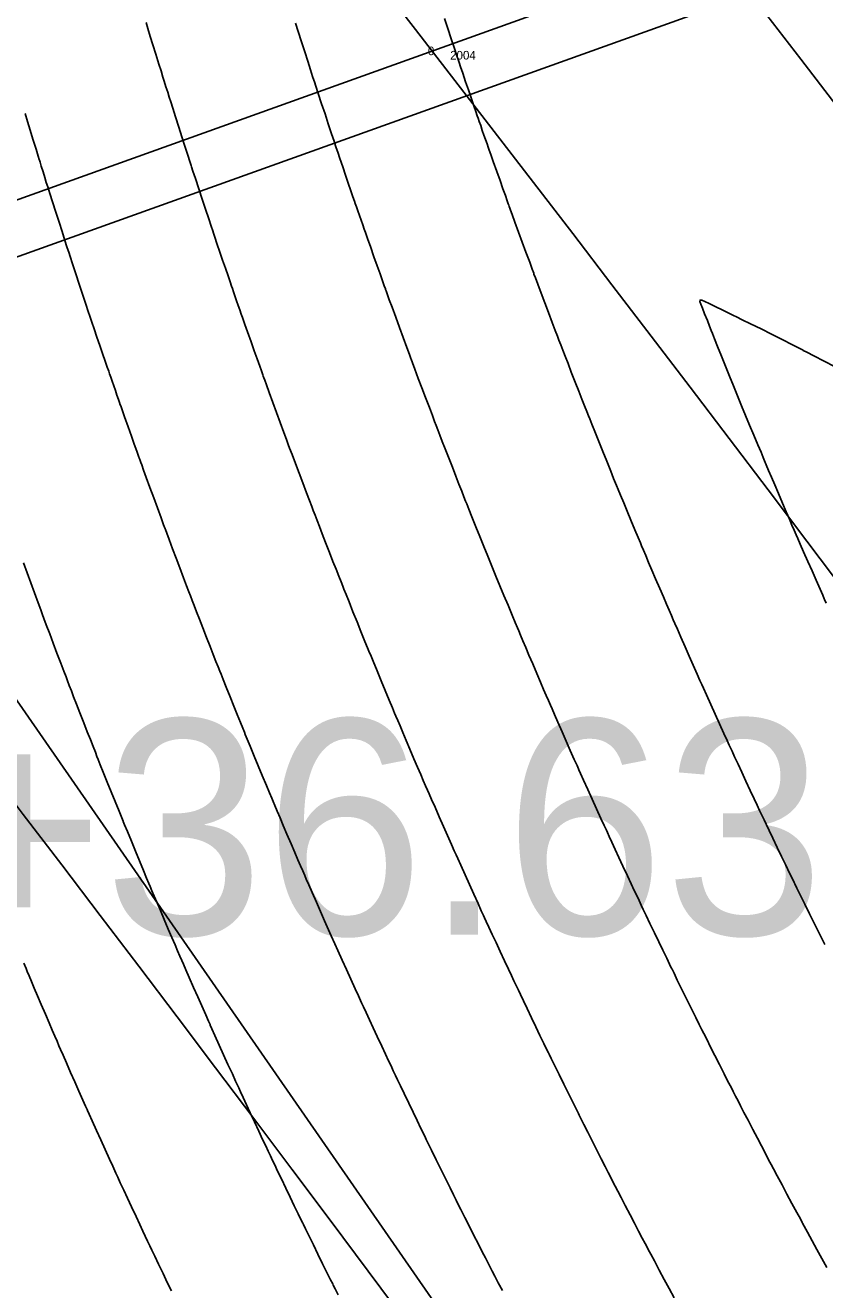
# Model space of a CAD drawing. Extents: x 74655 to 77873, y 48844 to 50507.
# Drawn here: x 75144.92 to 75156.06, y 49763.79 to 49781.42 of the extents above; entities that cross this region are included whole.
import ezdxf

# ---------------------------------------------------------------- set-up
doc = ezdxf.new("R2010")
doc.units = 0
for name, color, linetype in [('2', 7, 'Continuous'), ('24', 7, 'Continuous'), ('5', 7, 'Continuous'), ('50', 7, 'Continuous'), ('62', 7, 'Continuous'), ('7', 7, 'Continuous')]:
    doc.layers.add(name, color=color, linetype=linetype)

msp = doc.modelspace()

# ---------------------------------------------------------------- linework, layer by layer
at = {"layer": '2'}
for radius in [833.511, 829.511, 818.511, 807.511, 803.511]:
    msp.add_arc((74494.001, 49274.129), radius, 30.805045, 46.697858, dxfattribs=at)
at = {"layer": '5'}
msp.add_line((75052.613, 49904.932), (75166.591, 49740.588), dxfattribs=at)
at = {"layer": '50'}
for points in [[(75146.602, 49781.459), (75146.628, 49781.374), (75146.661, 49781.265), (75146.698, 49781.146), (75146.738, 49781.017), (75146.781, 49780.878), (75146.81, 49780.783), (75146.825, 49780.733), (75146.827, 49780.728), (75146.837, 49780.697), (75146.854, 49780.642), (75146.879, 49780.561), (75146.903, 49780.486), (75146.924, 49780.417), (75146.945, 49780.353), (75146.973, 49780.262), (75147.011, 49780.144), (75147.057, 49780), (75147.101, 49779.863), (75147.143, 49779.732), (75147.183, 49779.608), (75147.211, 49779.519), (75147.229, 49779.465), (75147.235, 49779.445), (75147.255, 49779.384), (75147.289, 49779.282), (75147.336, 49779.139), (75147.383, 49778.997), (75147.429, 49778.857), (75147.475, 49778.719), (75147.509, 49778.617), (75147.531, 49778.552), (75147.541, 49778.523), (75147.56, 49778.465), (75147.59, 49778.376), (75147.63, 49778.258), (75147.669, 49778.143), (75147.707, 49778.032), (75147.744, 49777.924), (75147.773, 49777.841), (75147.793, 49777.782), (75147.805, 49777.748), (75147.821, 49777.702), (75147.84, 49777.646), (75147.864, 49777.579), (75147.886, 49777.514), (75147.908, 49777.451), (75147.929, 49777.39), (75147.945, 49777.345), (75147.955, 49777.316), (75147.96, 49777.302), (75147.98, 49777.246), (75148.015, 49777.147), (75148.065, 49777.006), (75148.11, 49776.879), (75148.15, 49776.767), (75148.185, 49776.669), (75148.209, 49776.6), (75148.224, 49776.559), (75148.228, 49776.547), (75148.235, 49776.528), (75148.244, 49776.504), (75148.255, 49776.473), (75148.279, 49776.405), (75148.317, 49776.302), (75148.368, 49776.161), (75148.42, 49776.021), (75148.471, 49775.881), (75148.523, 49775.74), (75148.559, 49775.643), (75148.579, 49775.588), (75148.583, 49775.576), (75148.602, 49775.525), (75148.636, 49775.436), (75148.683, 49775.309), (75148.733, 49775.177), (75148.784, 49775.042), (75148.837, 49774.903), (75148.879, 49774.792), (75148.91, 49774.709), (75148.931, 49774.654), (75148.956, 49774.59), (75148.985, 49774.515), (75149.017, 49774.431), (75149.057, 49774.329), (75149.104, 49774.209), (75149.158, 49774.07), (75149.206, 49773.945), (75149.25, 49773.835), (75149.288, 49773.738), (75149.319, 49773.66), (75149.342, 49773.6), (75149.359, 49773.559), (75149.388, 49773.485), (75149.43, 49773.38), (75149.485, 49773.242), (75149.541, 49773.104), (75149.596, 49772.967), (75149.652, 49772.83), (75149.689, 49772.738), (75149.708, 49772.692), (75149.708, 49772.691), (75149.727, 49772.645), (75149.765, 49772.554), (75149.82, 49772.418), (75149.877, 49772.282), (75149.933, 49772.145), (75149.99, 49772.009), (75150.034, 49771.904), (75150.065, 49771.83), (75150.083, 49771.787), (75150.108, 49771.728), (75150.14, 49771.651), (75150.18, 49771.558), (75150.225, 49771.45), (75150.277, 49771.329), (75150.335, 49771.193), (75150.386, 49771.075), (75150.429, 49770.974), (75150.465, 49770.89), (75150.497, 49770.817), (75150.524, 49770.755), (75150.546, 49770.703), (75150.581, 49770.624), (75150.628, 49770.517), (75150.687, 49770.382), (75150.745, 49770.25), (75150.801, 49770.122), (75150.857, 49769.998), (75150.895, 49769.912), (75150.916, 49769.864), (75150.921, 49769.853), (75150.944, 49769.802), (75150.986, 49769.709), (75151.046, 49769.575), (75151.107, 49769.441), (75151.167, 49769.308), (75151.228, 49769.174), (75151.273, 49769.074), (75151.303, 49769.009), (75151.317, 49768.978), (75151.342, 49768.924), (75151.379, 49768.845), (75151.426, 49768.743), (75151.478, 49768.63), (75151.535, 49768.507), (75151.597, 49768.375), (75151.65, 49768.262), (75151.693, 49768.17), (75151.727, 49768.099), (75151.759, 49768.031), (75151.789, 49767.967), (75151.818, 49767.906), (75151.859, 49767.821), (75151.91, 49767.712), (75151.974, 49767.58), (75152.034, 49767.455), (75152.09, 49767.337), (75152.144, 49767.226), (75152.183, 49767.145), (75152.208, 49767.094), (75152.218, 49767.074), (75152.246, 49767.016), (75152.292, 49766.922), (75152.357, 49766.79), (75152.421, 49766.659), (75152.486, 49766.528), (75152.551, 49766.397), (75152.597, 49766.304), (75152.625, 49766.247), (75152.635, 49766.227), (75152.66, 49766.177), (75152.701, 49766.097), (75152.756, 49765.986), (75152.816, 49765.869), (75152.878, 49765.745), (75152.944, 49765.615), (75152.998, 49765.509), (75153.041, 49765.426), (75153.071, 49765.366), (75153.103, 49765.304), (75153.138, 49765.237), (75153.174, 49765.166), (75153.221, 49765.076), (75153.277, 49764.967), (75153.345, 49764.837), (75153.407, 49764.718), (75153.463, 49764.61), (75153.515, 49764.511), (75153.555, 49764.436), (75153.583, 49764.383), (75153.599, 49764.352), (75153.633, 49764.289), (75153.684, 49764.193), (75153.752, 49764.064), (75153.82, 49763.936), (75153.889, 49763.808), (75153.958, 49763.68)], [(75156.088, 49764.101), (75156.018, 49764.229), (75155.949, 49764.353), (75155.883, 49764.475), (75155.818, 49764.594), (75155.773, 49764.676), (75155.749, 49764.721), (75155.744, 49764.73), (75155.718, 49764.779), (75155.67, 49764.867), (75155.601, 49764.995), (75155.532, 49765.123), (75155.464, 49765.252), (75155.395, 49765.38), (75155.345, 49765.476), (75155.311, 49765.539), (75155.295, 49765.57), (75155.267, 49765.623), (75155.227, 49765.699), (75155.175, 49765.797), (75155.119, 49765.906), (75155.057, 49766.025), (75154.989, 49766.154), (75154.932, 49766.264), (75154.886, 49766.354), (75154.85, 49766.424), (75154.815, 49766.491), (75154.783, 49766.554), (75154.753, 49766.613), (75154.71, 49766.696), (75154.656, 49766.802), (75154.59, 49766.932), (75154.528, 49767.056), (75154.468, 49767.173), (75154.413, 49767.284), (75154.372, 49767.365), (75154.347, 49767.415), (75154.337, 49767.434), (75154.309, 49767.491), (75154.263, 49767.585), (75154.198, 49767.716), (75154.133, 49767.847), (75154.069, 49767.978), (75154.004, 49768.109), (75153.958, 49768.203), (75153.93, 49768.261), (75153.92, 49768.281), (75153.895, 49768.332), (75153.856, 49768.413), (75153.802, 49768.524), (75153.745, 49768.642), (75153.685, 49768.767), (75153.622, 49768.899), (75153.57, 49769.008), (75153.53, 49769.093), (75153.501, 49769.154), (75153.471, 49769.219), (75153.438, 49769.286), (75153.405, 49769.358), (75153.362, 49769.45), (75153.309, 49769.562), (75153.247, 49769.695), (75153.19, 49769.817), (75153.138, 49769.93), (75153.091, 49770.032), (75153.054, 49770.111), (75153.029, 49770.166), (75153.015, 49770.197), (75152.985, 49770.262), (75152.94, 49770.361), (75152.879, 49770.495), (75152.818, 49770.629), (75152.758, 49770.763), (75152.698, 49770.897), (75152.656, 49770.989), (75152.633, 49771.041), (75152.628, 49771.051), (75152.607, 49771.099), (75152.569, 49771.185), (75152.513, 49771.31), (75152.457, 49771.438), (75152.399, 49771.569), (75152.34, 49771.704), (75152.293, 49771.811), (75152.258, 49771.89), (75152.236, 49771.942), (75152.209, 49772.004), (75152.177, 49772.077), (75152.141, 49772.161), (75152.098, 49772.262), (75152.047, 49772.38), (75151.989, 49772.516), (75151.937, 49772.638), (75151.892, 49772.745), (75151.852, 49772.839), (75151.82, 49772.915), (75151.795, 49772.975), (75151.777, 49773.017), (75151.746, 49773.091), (75151.702, 49773.196), (75151.645, 49773.333), (75151.589, 49773.469), (75151.532, 49773.605), (75151.476, 49773.741), (75151.439, 49773.832), (75151.42, 49773.878), (75151.42, 49773.879), (75151.401, 49773.925), (75151.364, 49774.017), (75151.308, 49774.154), (75151.253, 49774.292), (75151.197, 49774.429), (75151.142, 49774.567), (75151.1, 49774.673), (75151.071, 49774.746), (75151.054, 49774.787), (75151.031, 49774.847), (75151, 49774.925), (75150.962, 49775.022), (75150.918, 49775.133), (75150.87, 49775.257), (75150.816, 49775.396), (75150.769, 49775.516), (75150.729, 49775.618), (75150.697, 49775.703), (75150.668, 49775.777), (75150.643, 49775.841), (75150.622, 49775.896), (75150.591, 49775.979), (75150.549, 49776.09), (75150.496, 49776.229), (75150.445, 49776.365), (75150.395, 49776.496), (75150.348, 49776.624), (75150.314, 49776.713), (75150.295, 49776.763), (75150.291, 49776.775), (75150.271, 49776.83), (75150.235, 49776.928), (75150.183, 49777.068), (75150.132, 49777.208), (75150.08, 49777.348), (75150.029, 49777.489), (75149.991, 49777.593), (75149.967, 49777.66), (75149.956, 49777.691), (75149.947, 49777.715), (75149.94, 49777.734), (75149.936, 49777.746), (75149.921, 49777.787), (75149.897, 49777.856), (75149.862, 49777.954), (75149.822, 49778.066), (75149.777, 49778.193), (75149.727, 49778.334), (75149.692, 49778.433), (75149.672, 49778.489), (75149.667, 49778.503), (75149.657, 49778.532), (75149.641, 49778.577), (75149.62, 49778.638), (75149.598, 49778.701), (75149.575, 49778.766), (75149.552, 49778.833), (75149.533, 49778.89), (75149.517, 49778.935), (75149.505, 49778.969), (75149.485, 49779.028), (75149.456, 49779.111), (75149.419, 49779.219), (75149.381, 49779.33), (75149.342, 49779.445), (75149.302, 49779.564), (75149.272, 49779.652), (75149.252, 49779.711), (75149.243, 49779.739), (75149.221, 49779.805), (75149.187, 49779.906), (75149.141, 49780.045), (75149.095, 49780.184), (75149.048, 49780.326), (75149.001, 49780.469), (75148.967, 49780.571), (75148.947, 49780.632), (75148.941, 49780.652), (75148.923, 49780.707), (75148.894, 49780.796), (75148.854, 49780.92), (75148.812, 49781.05), (75148.768, 49781.188), (75148.723, 49781.332), (75148.685, 49781.449)], [(75150.76, 49781.513), (75150.807, 49781.372), (75150.853, 49781.232), (75150.899, 49781.094), (75150.933, 49780.992), (75150.955, 49780.927), (75150.964, 49780.898), (75150.984, 49780.839), (75151.014, 49780.751), (75151.054, 49780.633), (75151.093, 49780.518), (75151.131, 49780.406), (75151.168, 49780.298), (75151.197, 49780.215), (75151.217, 49780.156), (75151.229, 49780.122), (75151.245, 49780.077), (75151.264, 49780.021), (75151.287, 49779.953), (75151.31, 49779.888), (75151.332, 49779.825), (75151.353, 49779.765), (75151.369, 49779.72), (75151.379, 49779.69), (75151.384, 49779.677), (75151.404, 49779.62), (75151.439, 49779.522), (75151.489, 49779.38), (75151.534, 49779.254), (75151.573, 49779.141), (75151.608, 49779.044), (75151.634, 49778.973), (75151.649, 49778.929), (75151.655, 49778.913), (75151.662, 49778.893), (75151.671, 49778.87), (75151.68, 49778.843), (75151.704, 49778.779), (75151.741, 49778.676), (75151.792, 49778.536), (75151.843, 49778.395), (75151.895, 49778.255), (75151.947, 49778.115), (75151.983, 49778.018), (75152.003, 49777.963), (75152.007, 49777.95), (75152.026, 49777.9), (75152.06, 49777.811), (75152.107, 49777.683), (75152.157, 49777.552), (75152.208, 49777.417), (75152.261, 49777.277), (75152.303, 49777.166), (75152.334, 49777.083), (75152.355, 49777.029), (75152.38, 49776.964), (75152.409, 49776.89), (75152.441, 49776.806), (75152.481, 49776.703), (75152.527, 49776.583), (75152.581, 49776.445), (75152.63, 49776.32), (75152.674, 49776.209), (75152.712, 49776.113), (75152.743, 49776.034), (75152.766, 49775.975), (75152.783, 49775.933), (75152.812, 49775.86), (75152.854, 49775.754), (75152.909, 49775.617), (75152.965, 49775.479), (75153.02, 49775.342), (75153.076, 49775.204), (75153.117, 49775.103), (75153.144, 49775.036), (75153.157, 49775.005), (75153.18, 49774.949), (75153.213, 49774.868), (75153.257, 49774.762), (75153.305, 49774.646), (75153.357, 49774.52), (75153.414, 49774.384), (75153.458, 49774.278), (75153.489, 49774.204), (75153.506, 49774.162), (75153.532, 49774.102), (75153.564, 49774.026), (75153.603, 49773.932), (75153.649, 49773.825), (75153.701, 49773.703), (75153.759, 49773.567), (75153.81, 49773.449), (75153.853, 49773.348), (75153.889, 49773.264), (75153.921, 49773.191), (75153.948, 49773.129), (75153.97, 49773.078), (75154.005, 49772.998), (75154.052, 49772.891), (75154.111, 49772.756), (75154.169, 49772.625), (75154.225, 49772.497), (75154.281, 49772.373), (75154.319, 49772.286), (75154.34, 49772.238), (75154.345, 49772.228), (75154.368, 49772.177), (75154.41, 49772.084), (75154.47, 49771.95), (75154.53, 49771.816), (75154.591, 49771.682), (75154.652, 49771.548), (75154.697, 49771.449), (75154.727, 49771.384), (75154.741, 49771.353), (75154.766, 49771.298), (75154.803, 49771.22), (75154.85, 49771.117), (75154.902, 49771.005), (75154.959, 49770.882), (75155.021, 49770.749), (75155.074, 49770.637), (75155.117, 49770.545), (75155.15, 49770.474), (75155.182, 49770.406), (75155.213, 49770.341), (75155.242, 49770.28), (75155.282, 49770.195), (75155.334, 49770.087), (75155.397, 49769.955), (75155.457, 49769.83), (75155.514, 49769.711), (75155.568, 49769.6), (75155.607, 49769.519), (75155.632, 49769.469), (75155.642, 49769.448), (75155.67, 49769.391), (75155.716, 49769.296), (75155.78, 49769.165), (75155.845, 49769.034), (75155.91, 49768.903), (75155.975, 49768.772), (75156.021, 49768.678), (75156.049, 49768.622), (75156.059, 49768.602)], [(75151.566, 49763.779), (75151.509, 49763.889), (75151.462, 49763.979), (75151.426, 49764.05), (75151.391, 49764.116), (75151.359, 49764.179), (75151.329, 49764.238), (75151.286, 49764.321), (75151.232, 49764.428), (75151.166, 49764.558), (75151.104, 49764.681), (75151.045, 49764.799), (75150.989, 49764.91), (75150.948, 49764.99), (75150.923, 49765.04), (75150.914, 49765.06), (75150.885, 49765.116), (75150.839, 49765.21), (75150.774, 49765.341), (75150.709, 49765.472), (75150.645, 49765.603), (75150.58, 49765.735), (75150.534, 49765.829), (75150.506, 49765.886), (75150.496, 49765.907), (75150.471, 49765.958), (75150.432, 49766.039), (75150.379, 49766.15), (75150.322, 49766.268), (75150.262, 49766.393), (75150.198, 49766.525), (75150.147, 49766.633), (75150.106, 49766.718), (75150.077, 49766.779), (75150.047, 49766.844), (75150.015, 49766.912), (75149.981, 49766.983), (75149.938, 49767.075), (75149.885, 49767.187), (75149.823, 49767.32), (75149.766, 49767.443), (75149.714, 49767.556), (75149.667, 49767.658), (75149.631, 49767.736), (75149.605, 49767.791), (75149.591, 49767.822), (75149.561, 49767.887), (75149.516, 49767.987), (75149.455, 49768.12), (75149.395, 49768.254), (75149.334, 49768.388), (75149.274, 49768.522), (75149.232, 49768.615), (75149.209, 49768.666), (75149.205, 49768.676), (75149.183, 49768.724), (75149.145, 49768.811), (75149.09, 49768.935), (75149.033, 49769.063), (75148.975, 49769.194), (75148.916, 49769.329), (75148.869, 49769.436), (75148.834, 49769.516), (75148.812, 49769.567), (75148.785, 49769.63), (75148.754, 49769.703), (75148.717, 49769.786), (75148.674, 49769.887), (75148.623, 49770.006), (75148.565, 49770.141), (75148.513, 49770.263), (75148.468, 49770.371), (75148.428, 49770.464), (75148.396, 49770.541), (75148.371, 49770.6), (75148.353, 49770.643), (75148.322, 49770.717), (75148.278, 49770.822), (75148.221, 49770.958), (75148.165, 49771.095), (75148.109, 49771.231), (75148.053, 49771.367), (75148.011, 49771.467), (75147.984, 49771.533), (75147.972, 49771.563), (75147.949, 49771.619), (75147.916, 49771.701), (75147.872, 49771.809), (75147.825, 49771.927), (75147.773, 49772.055), (75147.718, 49772.192), (75147.676, 49772.298), (75147.647, 49772.371), (75147.63, 49772.413), (75147.607, 49772.473), (75147.576, 49772.551), (75147.538, 49772.648), (75147.494, 49772.758), (75147.446, 49772.883), (75147.392, 49773.021), (75147.345, 49773.142), (75147.305, 49773.244), (75147.273, 49773.328), (75147.244, 49773.402), (75147.219, 49773.467), (75147.199, 49773.522), (75147.167, 49773.605), (75147.125, 49773.716), (75147.072, 49773.855), (75147.021, 49773.99), (75146.971, 49774.122), (75146.924, 49774.249), (75146.89, 49774.338), (75146.872, 49774.389), (75146.867, 49774.401), (75146.847, 49774.456), (75146.811, 49774.553), (75146.759, 49774.693), (75146.708, 49774.833), (75146.656, 49774.974), (75146.605, 49775.114), (75146.567, 49775.219), (75146.542, 49775.289), (75146.529, 49775.324), (75146.52, 49775.35), (75146.514, 49775.367), (75146.511, 49775.375), (75146.497, 49775.414), (75146.473, 49775.482), (75146.438, 49775.58), (75146.398, 49775.692), (75146.353, 49775.819), (75146.303, 49775.96), (75146.268, 49776.059), (75146.248, 49776.115), (75146.243, 49776.129), (75146.233, 49776.158), (75146.217, 49776.203), (75146.196, 49776.263), (75146.174, 49776.326), (75146.152, 49776.391), (75146.128, 49776.459), (75146.109, 49776.515), (75146.093, 49776.56), (75146.081, 49776.595), (75146.061, 49776.653), (75146.032, 49776.737), (75145.996, 49776.844), (75145.958, 49776.956), (75145.918, 49777.071), (75145.878, 49777.189), (75145.848, 49777.278), (75145.829, 49777.336), (75145.819, 49777.365), (75145.797, 49777.43), (75145.763, 49777.532), (75145.717, 49777.67), (75145.671, 49777.81), (75145.624, 49777.952), (75145.577, 49778.095), (75145.543, 49778.197), (75145.524, 49778.258), (75145.517, 49778.278), (75145.499, 49778.332), (75145.471, 49778.421), (75145.431, 49778.545), (75145.389, 49778.676), (75145.345, 49778.813), (75145.299, 49778.957), (75145.261, 49779.075), (75145.233, 49779.165), (75145.212, 49779.229), (75145.191, 49779.299), (75145.167, 49779.374), (75145.142, 49779.454), (75145.125, 49779.51), (75145.115, 49779.54), (75145.113, 49779.546), (75145.098, 49779.596), (75145.069, 49779.691), (75145.026, 49779.83), (75144.986, 49779.959), (75144.949, 49780.078), (75144.916, 49780.187)], [(75156.08, 49773.364), (75156.057, 49773.415), (75156.052, 49773.425), (75156.031, 49773.474), (75155.992, 49773.56), (75155.937, 49773.684), (75155.881, 49773.812), (75155.823, 49773.944), (75155.764, 49774.078), (75155.717, 49774.185), (75155.682, 49774.265), (75155.66, 49774.316), (75155.633, 49774.379), (75155.601, 49774.452), (75155.565, 49774.535), (75155.522, 49774.636), (75155.471, 49774.755), (75155.413, 49774.89), (75155.361, 49775.012), (75155.315, 49775.12), (75155.276, 49775.213), (75155.244, 49775.29), (75155.218, 49775.349), (75155.201, 49775.392), (75155.17, 49775.466), (75155.126, 49775.571), (75155.069, 49775.707), (75155.012, 49775.844), (75154.956, 49775.98), (75154.9, 49776.116), (75154.863, 49776.207), (75154.844, 49776.253), (75154.844, 49776.254), (75154.825, 49776.3), (75154.788, 49776.392), (75154.732, 49776.529), (75154.676, 49776.666), (75154.621, 49776.804), (75154.566, 49776.941), (75154.524, 49777.047), (75154.494, 49777.121), (75154.477, 49777.164), (75154.454, 49777.224), (75154.423, 49777.302), (75154.385, 49777.398), (75154.355, 49777.474), (75154.332, 49777.532), (75154.317, 49777.57), (75154.321, 49777.589), (75154.344, 49777.589), (75154.386, 49777.569), (75154.448, 49777.539), (75154.532, 49777.498), (75154.637, 49777.448), (75154.721, 49777.407), (75154.786, 49777.375), (75154.83, 49777.353), (75154.909, 49777.314), (75155.023, 49777.258), (75155.171, 49777.185), (75155.318, 49777.111), (75155.465, 49777.037), (75155.611, 49776.963), (75155.709, 49776.913), (75155.758, 49776.888), (75155.759, 49776.887), (75155.808, 49776.862), (75155.904, 49776.812), (75156.048, 49776.737), (75156.192, 49776.662)], [(75149.277, 49763.722), (75149.237, 49763.803), (75149.211, 49763.853), (75149.202, 49763.872), (75149.173, 49763.929), (75149.127, 49764.023), (75149.062, 49764.154), (75148.997, 49764.285), (75148.933, 49764.416), (75148.868, 49764.547), (75148.822, 49764.642), (75148.794, 49764.699), (75148.784, 49764.72), (75148.76, 49764.77), (75148.72, 49764.851), (75148.667, 49764.962), (75148.61, 49765.081), (75148.55, 49765.206), (75148.487, 49765.338), (75148.435, 49765.446), (75148.394, 49765.531), (75148.365, 49765.592), (75148.335, 49765.657), (75148.303, 49765.725), (75148.269, 49765.796), (75148.226, 49765.888), (75148.173, 49766), (75148.111, 49766.133), (75148.054, 49766.256), (75148.002, 49766.368), (75147.955, 49766.471), (75147.919, 49766.549), (75147.893, 49766.604), (75147.879, 49766.635), (75147.85, 49766.7), (75147.804, 49766.799), (75147.743, 49766.933), (75147.683, 49767.067), (75147.622, 49767.201), (75147.562, 49767.335), (75147.52, 49767.428), (75147.497, 49767.479), (75147.493, 49767.489), (75147.471, 49767.537), (75147.433, 49767.624), (75147.378, 49767.748), (75147.321, 49767.876), (75147.263, 49768.007), (75147.204, 49768.142), (75147.157, 49768.249), (75147.123, 49768.328), (75147.1, 49768.38), (75147.073, 49768.442), (75147.042, 49768.515), (75147.005, 49768.599), (75146.962, 49768.7), (75146.911, 49768.818), (75146.853, 49768.954), (75146.801, 49769.076), (75146.756, 49769.183), (75146.716, 49769.277), (75146.684, 49769.353), (75146.659, 49769.413), (75146.641, 49769.455), (75146.61, 49769.529), (75146.566, 49769.634), (75146.509, 49769.771), (75146.453, 49769.907), (75146.397, 49770.043), (75146.341, 49770.179), (75146.303, 49770.271), (75146.283, 49770.32), (75146.281, 49770.324), (75146.262, 49770.371), (75146.225, 49770.462), (75146.171, 49770.596), (75146.116, 49770.731), (75146.062, 49770.867), (75146.006, 49771.005), (75145.964, 49771.111), (75145.935, 49771.184), (75145.918, 49771.226), (75145.895, 49771.285), (75145.864, 49771.364), (75145.826, 49771.46), (75145.782, 49771.571), (75145.734, 49771.696), (75145.68, 49771.834), (75145.633, 49771.954), (75145.593, 49772.057), (75145.561, 49772.141), (75145.532, 49772.215), (75145.508, 49772.28), (75145.487, 49772.334), (75145.455, 49772.417), (75145.413, 49772.528), (75145.36, 49772.668), (75145.309, 49772.803), (75145.26, 49772.934), (75145.212, 49773.062), (75145.179, 49773.151), (75145.16, 49773.201), (75145.155, 49773.214), (75145.135, 49773.268), (75145.099, 49773.366), (75145.047, 49773.506), (75144.996, 49773.646), (75144.944, 49773.787), (75144.893, 49773.927)], [(75144.898, 49768.342), (75144.929, 49768.268), (75144.947, 49768.226), (75144.972, 49768.166), (75145.004, 49768.09), (75145.044, 49767.996), (75145.09, 49767.888), (75145.141, 49767.767), (75145.199, 49767.631), (75145.25, 49767.513), (75145.294, 49767.412), (75145.33, 49767.328), (75145.361, 49767.255), (75145.388, 49767.193), (75145.411, 49767.141), (75145.445, 49767.062), (75145.492, 49766.955), (75145.551, 49766.82), (75145.609, 49766.689), (75145.666, 49766.561), (75145.721, 49766.436), (75145.759, 49766.35), (75145.781, 49766.302), (75145.785, 49766.292), (75145.808, 49766.24), (75145.85, 49766.148), (75145.91, 49766.013), (75145.971, 49765.88), (75146.031, 49765.746), (75146.092, 49765.612), (75146.138, 49765.513), (75146.167, 49765.448), (75146.181, 49765.417), (75146.207, 49765.362), (75146.243, 49765.283), (75146.29, 49765.181), (75146.342, 49765.068), (75146.4, 49764.946), (75146.462, 49764.813), (75146.514, 49764.7), (75146.557, 49764.609), (75146.591, 49764.537), (75146.623, 49764.47), (75146.653, 49764.405), (75146.682, 49764.344), (75146.723, 49764.259), (75146.775, 49764.15), (75146.838, 49764.018), (75146.898, 49763.893), (75146.955, 49763.775)]]:
    msp.add_lwpolyline(points, dxfattribs=at)
at = {"layer": '7'}
for p, q in [((74963.653, 49713.973), (75340.141, 49849.089)), ((74963.906, 49713.267), (75340.394, 49848.383))]:
    msp.add_line(p, q, dxfattribs=at)

# ---------------------------------------------------------------- texts
at = {"layer": '24'}
msp.add_text('STA 83+36.63', height=3, dxfattribs=at).set_placement((75130.295, 49768.74))
at = {"layer": '62'}
for s, p in [('0', (75150.529, 49781.002)), ('2004', (75150.839, 49780.942))]:
    msp.add_text(s, height=0.12, dxfattribs=at).set_placement(p)

doc.saveas('drawing.dxf')
